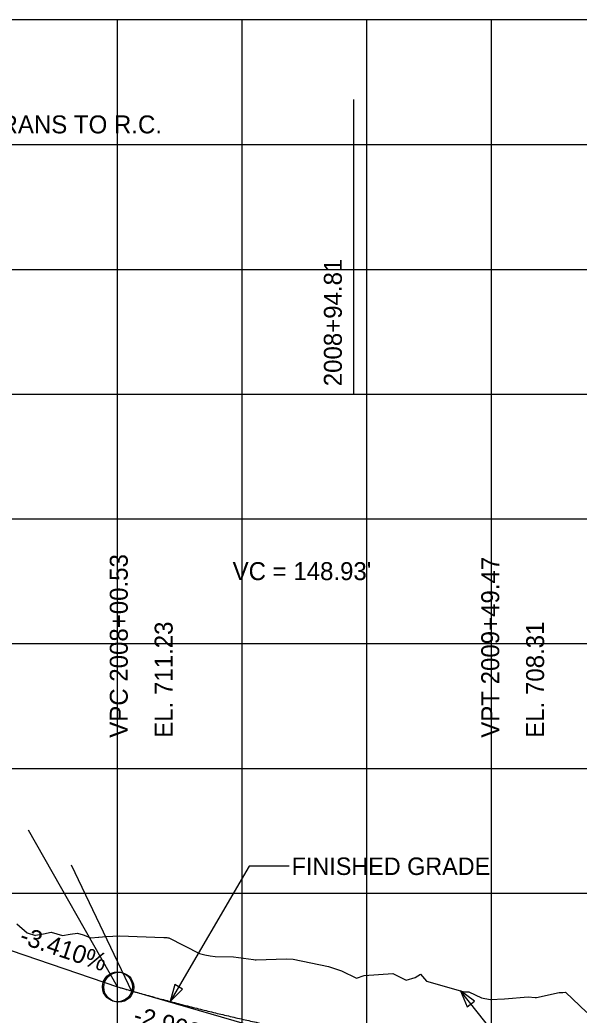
# Model space of a CAD drawing. Extents: x -7164 to 2214450, y -19642 to 253469.
# Drawn here: x 6760.9 to 6985.1, y 601.1 to 1000 of the extents above; entities that cross this region are included whole.
import ezdxf

# ---------------------------------------------------------------- set-up
doc = ezdxf.new("R2010")
doc.units = 0
for name, color, linetype in [('DESIGN - PROFILE - Proposed', 7, 'Continuous'), ('DESIGN - PROFILE - Proposed Curve Text', 7, 'Continuous'), ('DESIGN - PROFILE - Proposed Text', 7, 'Continuous'), ('DESIGN - SCRATCH - User 1', 7, 'Continuous'), ('DESIGN - SHEET - Light Grid', 7, 'Continuous'), ('SURVEY - PROFILE - Ground Line with Text', 7, 'Continuous')]:
    doc.layers.add(name, color=color, linetype=linetype)

msp = doc.modelspace()

# ---------------------------------------------------------------- linework, layer by layer
at = {"layer": 'DESIGN - PROFILE - Proposed'}
for p, q in [((6750, 629.48), (6800, 612.43)), ((6750, 629.48), (6800, 612.43)), ((6800, 612.43), (6800.53, 612.27)), ((6800, 612.43), (6800.53, 612.27))]:
    msp.add_line(p, q, dxfattribs=at)
msp.add_spline([(6800.53, 612.27), (6803.51, 611.42), (6806.49, 610.57), (6809.47, 609.73), (6812.45, 608.91), (6815.43, 608.09), (6818.41, 607.29), (6821.38, 606.5), (6824.36, 605.72), (6827.34, 604.95), (6830.32, 604.2), (6833.3, 603.45), (6836.28, 602.72), (6839.26, 601.99), (6842.23, 601.28), (6845.21, 600.58), (6848.19, 599.89), (6851.17, 599.21), (6854.15, 598.54), (6857.13, 597.89), (6860.11, 597.24), (6863.09, 596.61), (6866.06, 595.99), (6869.04, 595.38), (6872.02, 594.78), (6875, 594.19), (6877.98, 593.61), (6880.96, 593.04), (6883.94, 592.49), (6886.91, 591.95), (6889.89, 591.41), (6892.87, 590.89), (6895.85, 590.38), (6898.83, 589.88), (6901.81, 589.4), (6904.79, 588.92), (6907.77, 588.45), (6910.74, 588), (6913.72, 587.56), (6916.7, 587.13), (6919.68, 586.71), (6922.66, 586.3), (6925.64, 585.9), (6928.62, 585.51), (6931.59, 585.14), (6934.57, 584.77), (6937.55, 584.42), (6940.53, 584.08), (6943.51, 583.75), (6946.49, 583.43), (6949.47, 583.12)], degree=3, dxfattribs=at)
msp.add_spline([(6800.53, 612.27), (6803.51, 611.42), (6806.49, 610.57), (6809.47, 609.73), (6812.45, 608.91), (6815.43, 608.09), (6818.41, 607.29), (6821.38, 606.5), (6824.36, 605.72), (6827.34, 604.95), (6830.32, 604.2), (6833.3, 603.45), (6836.28, 602.72), (6839.26, 601.99), (6842.23, 601.28), (6845.21, 600.58), (6848.19, 599.89), (6851.17, 599.21), (6854.15, 598.54), (6857.13, 597.89), (6860.11, 597.24), (6863.09, 596.61), (6866.06, 595.99), (6869.04, 595.38), (6872.02, 594.78), (6875, 594.19), (6877.98, 593.61), (6880.96, 593.04), (6883.94, 592.49), (6886.91, 591.95), (6889.89, 591.41), (6892.87, 590.89), (6895.85, 590.38), (6898.83, 589.88), (6901.81, 589.4), (6904.79, 588.92), (6907.77, 588.45), (6910.74, 588), (6913.72, 587.56), (6916.7, 587.13), (6919.68, 586.71), (6922.66, 586.3), (6925.64, 585.9), (6928.62, 585.51), (6931.59, 585.14), (6934.57, 584.77), (6937.55, 584.42), (6940.53, 584.08), (6943.51, 583.75), (6946.49, 583.43), (6949.47, 583.12)], degree=3, dxfattribs=at)
at = {"layer": 'DESIGN - PROFILE - Proposed Curve Text'}
for p, q in [((6894.81, 850), (6894.81, 968.1)), ((6894.81, 850), (6894.81, 968.1)), ((6672.59, 950), (6894.81, 950)), ((6672.59, 950), (6894.81, 950)), ((6894.81, 950), (7401.82, 950)), ((6894.81, 950), (7401.82, 950))]:
    msp.add_line(p, q, dxfattribs=at)
at = {"layer": 'DESIGN - PROFILE - Proposed Text'}
msp.add_line((6800.53, 612.27), (6869.24, 592.35), dxfattribs=at)
msp.add_line((6800.53, 612.27), (6869.24, 592.35), dxfattribs=at)
for points in [[(6868.88, 660.77), (6852.76, 660.77), (6821.11, 606.57)], [(6868.88, 660.77), (6852.76, 660.77), (6821.11, 606.57)], [(6984.23, 564.18), (6974.52, 564.18), (6937.51, 610.87)], [(6984.23, 564.18), (6974.52, 564.18), (6937.51, 610.87)]]:
    msp.add_lwpolyline(points, dxfattribs=at)
for points in [[(6822.96, 613.33), (6821.11, 606.57), (6826.09, 611.5)], [(6822.96, 613.33), (6821.11, 606.57), (6826.09, 611.5)], [(6943.13, 606.69), (6937.51, 610.87), (6940.29, 604.44)], [(6943.13, 606.69), (6937.51, 610.87), (6940.29, 604.44)]]:
    msp.add_lwpolyline(points, close=True, dxfattribs=at)
for centre in [(6800, 612.43), (6800, 612.43), (6800.53, 612.27), (6800.53, 612.27)]:
    msp.add_circle(centre, 6, dxfattribs=at)
at = {"layer": 'DESIGN - SCRATCH - User 1'}
for p, q in [((9700, 1000), (6000, 1000)), ((9700, 1000), (6000, 1000)), ((6800, 612.43), (6764.33, 675.27)), ((6800, 612.43), (6764.33, 675.27)), ((6805.92, 610.27), (6781.63, 661.18)), ((6805.92, 610.27), (6781.63, 661.18))]:
    msp.add_line(p, q, dxfattribs=at)
at = {"layer": 'DESIGN - SHEET - Light Grid'}
for p, q in [((6800, 0), (6800, 1000)), ((6800, 0), (6800, 1000)), ((6850, 0), (6850, 1000)), ((6850, 0), (6850, 1000)), ((6900, 0), (6900, 1000)), ((6900, 0), (6900, 1000)), ((6950, 0), (6950, 1000)), ((6950, 0), (6950, 1000)), ((6000, 950), (9700, 950)), ((6000, 950), (9700, 950)), ((6000, 900), (9700, 900)), ((6000, 900), (9700, 900)), ((6000, 850), (9700, 850)), ((6000, 850), (9700, 850)), ((6000, 800), (9700, 800)), ((6000, 800), (9700, 800)), ((6000, 750), (9700, 750)), ((6000, 750), (9700, 750)), ((6000, 700), (9700, 700)), ((6000, 700), (9700, 700)), ((6000, 650), (9700, 650)), ((6000, 650), (9700, 650))]:
    msp.add_line(p, q, dxfattribs=at)
at = {"layer": 'SURVEY - PROFILE - Ground Line with Text'}
msp.add_lwpolyline([(6759.67, 637.71), (6763.83, 634.08), (6767.18, 633.07), (6767.2, 633.08), (6770.41, 633.73), (6773.36, 634.33), (6777.96, 633.02), (6781.08, 633.51), (6783.98, 633.97), (6786.26, 633.27), (6789.28, 632.05), (6792.43, 632.4), (6792.47, 632.4), (6795.42, 632.55), (6798.21, 632.69), (6800.84, 632.82), (6818.62, 632.23), (6819.13, 632.24), (6819.59, 632.26), (6819.77, 632.22), (6820.19, 632.13), (6820.59, 632.05), (6832.93, 625.77), (6835.08, 625.3), (6837.19, 624.83), (6839.21, 624.57), (6846.53, 624.45), (6854.49, 623.45), (6855.2, 623.27), (6855.42, 623.24), (6855.62, 623.23), (6867.62, 623.67), (6870.47, 623.51), (6884.68, 620.65), (6889.82, 618.78), (6895.88, 615.96), (6898.91, 616.93), (6910.36, 617.78), (6915.77, 615.17), (6919.33, 616.22), (6921.57, 617.47), (6923.91, 614.71), (6937.51, 610.87), (6939.2, 610.4), (6940.84, 610.4), (6945.93, 608.07), (6949.4, 607.35), (6955.24, 607.6), (6964.68, 608.48), (6967.51, 608.1), (6967.56, 608.1), (6967.99, 608.13), (6977.05, 610.16), (6977.76, 610.19), (6978.59, 610.22), (6979.59, 610.26), (6988.19, 602.21)], dxfattribs=at)
msp.add_lwpolyline([(6759.67, 637.71), (6763.83, 634.08), (6767.18, 633.07), (6767.2, 633.08), (6770.41, 633.73), (6773.36, 634.33), (6777.96, 633.02), (6781.08, 633.51), (6783.98, 633.97), (6786.26, 633.27), (6789.28, 632.05), (6792.43, 632.4), (6792.47, 632.4), (6795.42, 632.55), (6798.21, 632.69), (6800.84, 632.82), (6818.62, 632.23), (6819.13, 632.24), (6819.59, 632.26), (6819.77, 632.22), (6820.19, 632.13), (6820.59, 632.05), (6832.93, 625.77), (6835.08, 625.3), (6837.19, 624.83), (6839.21, 624.57), (6846.53, 624.45), (6854.49, 623.45), (6855.2, 623.27), (6855.42, 623.24), (6855.62, 623.23), (6867.62, 623.67), (6870.47, 623.51), (6884.68, 620.65), (6889.82, 618.78), (6895.88, 615.96), (6898.91, 616.93), (6910.36, 617.78), (6915.77, 615.17), (6919.33, 616.22), (6921.57, 617.47), (6923.91, 614.71), (6937.51, 610.87), (6939.2, 610.4), (6940.84, 610.4), (6945.93, 608.07), (6949.4, 607.35), (6955.24, 607.6), (6964.68, 608.48), (6967.51, 608.1), (6967.56, 608.1), (6967.99, 608.13), (6977.05, 610.16), (6977.76, 610.19), (6978.59, 610.22), (6979.59, 610.26), (6988.19, 602.21)], dxfattribs=at)
msp.add_lwpolyline([(6759.67, 637.71), (6763.83, 634.08), (6767.18, 633.07), (6767.2, 633.08), (6770.41, 633.73), (6773.36, 634.33), (6777.96, 633.02), (6781.08, 633.51), (6783.98, 633.97), (6786.26, 633.27), (6789.28, 632.05), (6792.43, 632.4), (6792.47, 632.4), (6795.42, 632.55), (6798.21, 632.69), (6800.84, 632.82), (6818.62, 632.23), (6819.13, 632.24), (6819.59, 632.26), (6819.77, 632.22), (6820.19, 632.13), (6820.59, 632.05), (6832.93, 625.77), (6835.08, 625.3), (6837.19, 624.83), (6839.21, 624.57), (6846.53, 624.45), (6854.49, 623.45), (6855.2, 623.27), (6855.42, 623.24), (6855.62, 623.23), (6867.62, 623.67), (6870.47, 623.51), (6884.68, 620.65), (6889.82, 618.78), (6895.88, 615.96), (6898.91, 616.93), (6910.36, 617.78), (6915.77, 615.17), (6919.33, 616.22), (6921.57, 617.47), (6923.91, 614.71), (6937.51, 610.87), (6939.2, 610.4), (6940.84, 610.4), (6945.93, 608.07), (6949.4, 607.35), (6955.24, 607.6), (6964.68, 608.48), (6967.51, 608.1), (6967.56, 608.1), (6967.99, 608.13), (6977.05, 610.16), (6977.76, 610.19), (6978.59, 610.22), (6979.59, 610.26), (6988.19, 602.21)], dxfattribs=at)
msp.add_lwpolyline([(6759.67, 637.71), (6763.83, 634.08), (6767.18, 633.07), (6767.2, 633.08), (6770.41, 633.73), (6773.36, 634.33), (6777.96, 633.02), (6781.08, 633.51), (6783.98, 633.97), (6786.26, 633.27), (6789.28, 632.05), (6792.43, 632.4), (6792.47, 632.4), (6795.42, 632.55), (6798.21, 632.69), (6800.84, 632.82), (6818.62, 632.23), (6819.13, 632.24), (6819.59, 632.26), (6819.77, 632.22), (6820.19, 632.13), (6820.59, 632.05), (6832.93, 625.77), (6835.08, 625.3), (6837.19, 624.83), (6839.21, 624.57), (6846.53, 624.45), (6854.49, 623.45), (6855.2, 623.27), (6855.42, 623.24), (6855.62, 623.23), (6867.62, 623.67), (6870.47, 623.51), (6884.68, 620.65), (6889.82, 618.78), (6895.88, 615.96), (6898.91, 616.93), (6910.36, 617.78), (6915.77, 615.17), (6919.33, 616.22), (6921.57, 617.47), (6923.91, 614.71), (6937.51, 610.87), (6939.2, 610.4), (6940.84, 610.4), (6945.93, 608.07), (6949.4, 607.35), (6955.24, 607.6), (6964.68, 608.48), (6967.51, 608.1), (6967.56, 608.1), (6967.99, 608.13), (6977.05, 610.16), (6977.76, 610.19), (6978.59, 610.22), (6979.59, 610.26), (6988.19, 602.21)], dxfattribs=at)

# ---------------------------------------------------------------- texts
at = {"layer": 'DESIGN - PROFILE - Proposed Curve Text'}
for s, p in [('TRANS TO R.C.', (6747.25, 954.51)), ("VC = 148.93'", (6846.18, 775.45)), ("VC = 148.93'", (6846.18, 775.45))]:
    msp.add_text(s, height=7.2, dxfattribs=at).set_placement(p)
for s, rotation, p in [('TRANS TO R.C.', 360, (6747.25, 954.51)), ('2008+94.81', 90, (6889.97, 853.16)), ('2008+94.81', 90, (6889.97, 853.16))]:
    msp.add_text(s, height=7.2, rotation=rotation, dxfattribs=at).set_placement(p)
at = {"layer": 'DESIGN - PROFILE - Proposed Text'}
for s, rotation, p in [('VPC 2008+00.53 ', 90, (6804.13, 712.27)), ('VPC 2008+00.53 ', 90, (6804.13, 712.27)), ('VPT 2009+49.47 ', 90, (6953.07, 712.27)), ('VPT 2009+49.47 ', 90, (6953.07, 712.27)), ('EL. 711.23', 90, (6822.13, 712.27)), ('EL. 711.23', 90, (6822.13, 712.27)), ('EL. 708.31', 90, (6971.07, 712.27)), ('EL. 708.31', 90, (6971.07, 712.27)), ('-3.410%', 341.1721, (6760.29, 630.1)), ('-3.410%', 341.1721, (6760.29, 630.1)), ('-2.900%', 343.8278, (6805.89, 598.02)), ('-2.900%', 343.8278, (6805.89, 598.02))]:
    msp.add_text(s, height=7.2, rotation=rotation, dxfattribs=at).set_placement(p)
msp.add_text('FINISHED GRADE', height=7, dxfattribs=at).set_placement((6869.88, 657.27))
msp.add_text('FINISHED GRADE', height=7, dxfattribs=at).set_placement((6869.88, 657.27))

doc.saveas('drawing.dxf')
